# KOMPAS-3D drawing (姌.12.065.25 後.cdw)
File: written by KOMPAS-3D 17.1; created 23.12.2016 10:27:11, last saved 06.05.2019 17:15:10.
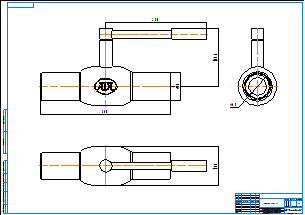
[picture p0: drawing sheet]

Sheet 1: A1, landscape

Title block, sheet 1: name: КШ.12.065.25 сс; material: Внимание! Данный продукт является объектом авторского права ООО «Торговый Дом АДЛ». / Запрещается изменение, копирование, распространение / (в том числе путем копирования на другие сайты и ресурсы в Интернете) / или любое иное использование информации и объектов без предварительного / согласия правообладателя (ООО «Торговый Дом АДЛ»).; sheets: 1; organisation: ООО "Торговый дом АДЛ"; sheet format: A1; stored path: C:\Users\tra\Desktop\2д чертежи\Шаровые краны БИВАЛ\КШ_Бивал_серия_11_12\KOMPAS_2D\КШ.12.065.25 сс.cdw

Views: Вид 1, Проекционный вид 2, Проекционный вид 3
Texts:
  Klimkovich
  ADL
Dimensions and other numbers on the sheet: 360; 76; 159,3; 280; 68; 108; 1:1; 1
